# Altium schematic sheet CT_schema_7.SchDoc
size 254 x 245 mm
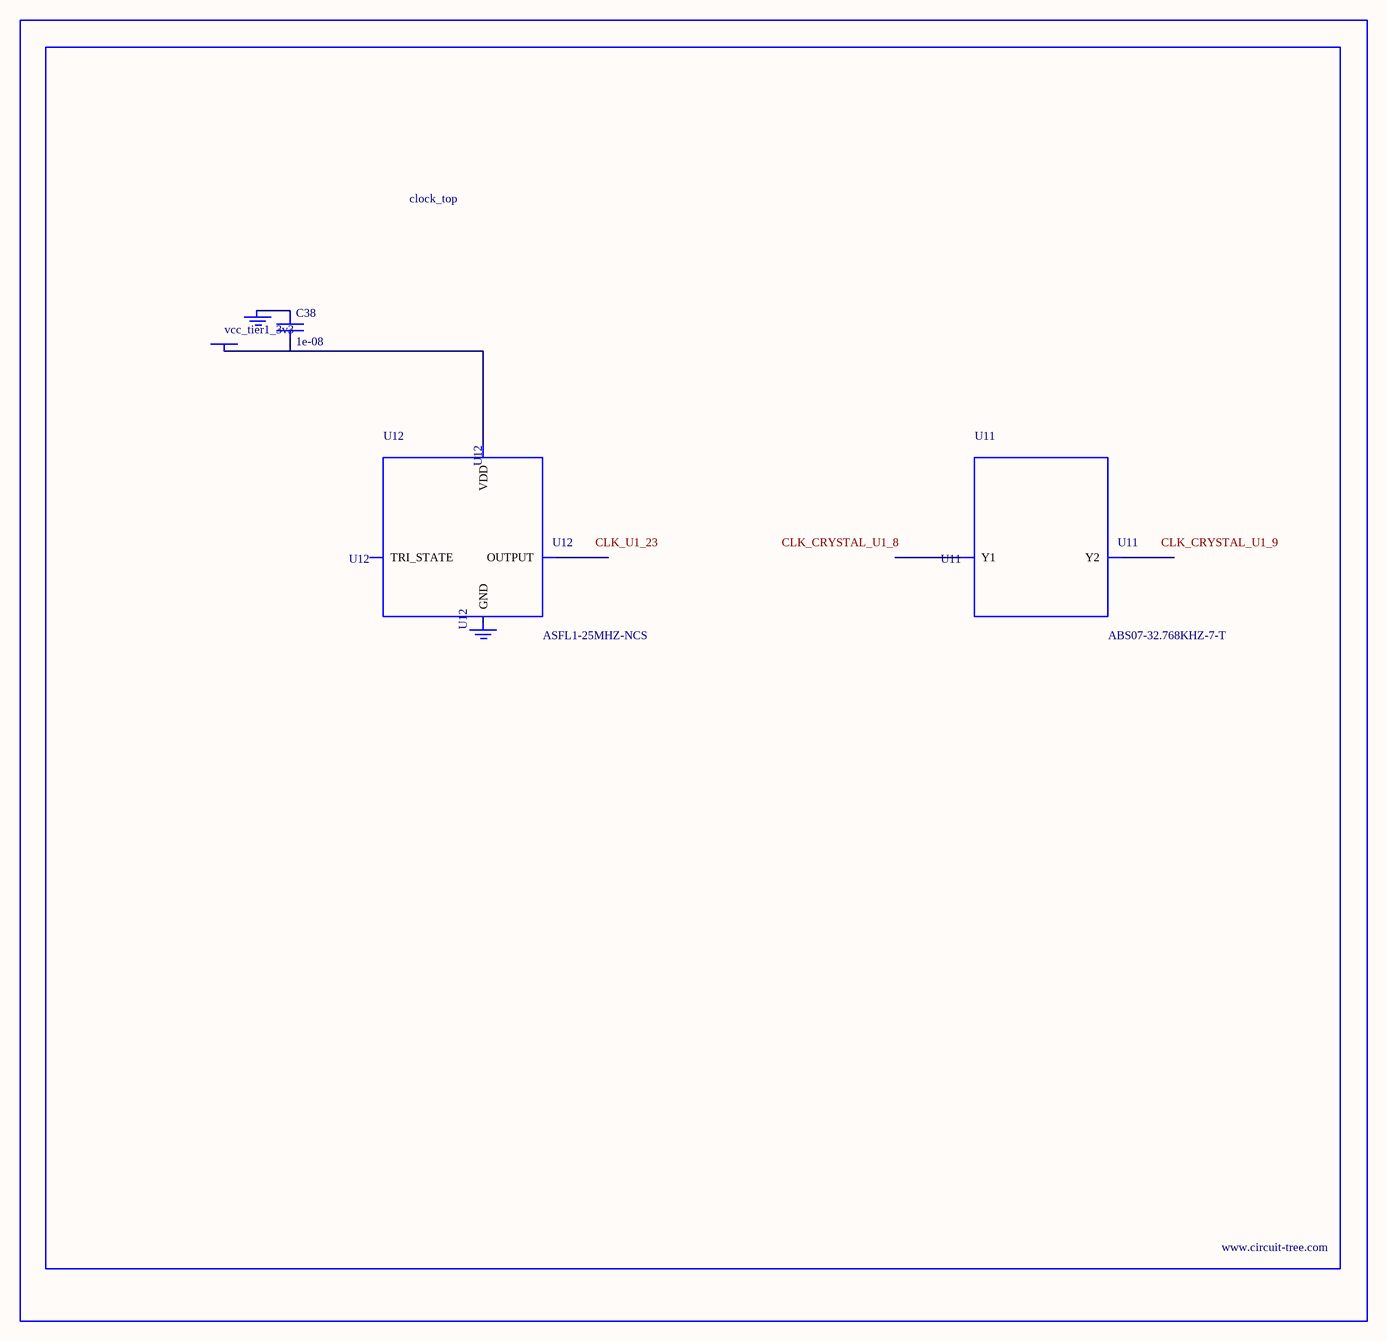
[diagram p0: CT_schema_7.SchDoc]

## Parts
BORDER6  (no value)
C38  1e-08  [C0402]
GND_INSTANCE_6_0  (no value)
GND_INSTANCE_6_1  (no value)
POWER_INSTANCE_6_0  vcc_tier1_3v3
U11  ABS07-32.768KHZ-7-T  [ABS07-32.768KHZ-7-T]
U12  ASFL1-25MHZ-NCS  [ASFL1]

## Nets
NetC38_1: C38.1 GND_INSTANCE_6_0.0(GND)
NetC38_2: C38.2 POWER_INSTANCE_6_0.0(PWR) U12.4(VDD)

Not connected (* = marked no-connect by the designer): GND_INSTANCE_6_1 0(GND); U11 1(Y1) 2(Y2); U12 1(TRI_STATE) 2(GND) 3(OUTPUT)

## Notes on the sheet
- Labels drawn without touching a wire or pin: CLK_CRYSTAL_U1_8, CLK_CRYSTAL_U1_9, CLK_U1_23

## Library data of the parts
BORDER6 = BORDER_PAGE6
C38 = C0402C103K3RAC
GND_INSTANCE_6_0 GND_INSTANCE_6_1 = GND
POWER_INSTANCE_6_0 = PWR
